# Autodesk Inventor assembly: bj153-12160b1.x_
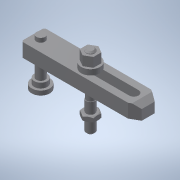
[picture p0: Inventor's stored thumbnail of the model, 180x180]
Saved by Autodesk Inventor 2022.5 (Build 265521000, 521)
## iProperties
Part Number: bj153-12160b1.x_
Material: 一般
Document SubType Name: Assembly
Designer: ImaoCorp
Sending System: SOLIDWORKS 2017-2017317
MC: AMD64
MC_MODEL: Intel64 Family 6 Model 60 Stepping 3, GenuineIntel
OS: Windows_NT
FRU: Parasolid Version 29.0, build 201,  4-17-2017
FORMAT: text
GUISE: transmit
KEY: bj153-12160b1
FILE: bj153-12160b1.x_t
DATE: Fri Mar 15 10:24:26 2019
Author: ImaoCorp
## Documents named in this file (6)
- X:\14_SW2022-Inv2022\00_全2023-1023新製品(TCC)まで\b\bj153-12160b1\BJ153-12160B1.iam
- X:\14_SW2022-Inv2022\00_全2023-1023新製品(TCC)まで\b\bj153-12160b1\bj153-12160b1_01.ipt
- X:\14_SW2022-Inv2022\00_全2023-1023新製品(TCC)まで\b\bj153-12160b1\bj153-12160b1_02.ipt
- X:\14_SW2022-Inv2022\00_全2023-1023新製品(TCC)まで\b\bj153-12160b1\bj153-12160b1_03.ipt
- X:\14_SW2022-Inv2022\00_全2023-1023新製品(TCC)まで\b\bj153-12160b1\bj153-12160b1_04.ipt
- X:\14_SW2022-Inv2022\00_全2023-1023新製品(TCC)まで\b\bj153-12160b1\bj153-12160b1_05.ipt
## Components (5 placed, 5 different names)
1. bj153-12160b1_01
2. bj153-12160b1_02
3. bj153-12160b1_03
4. bj153-12160b1_04
5. bj153-12160b1_05
